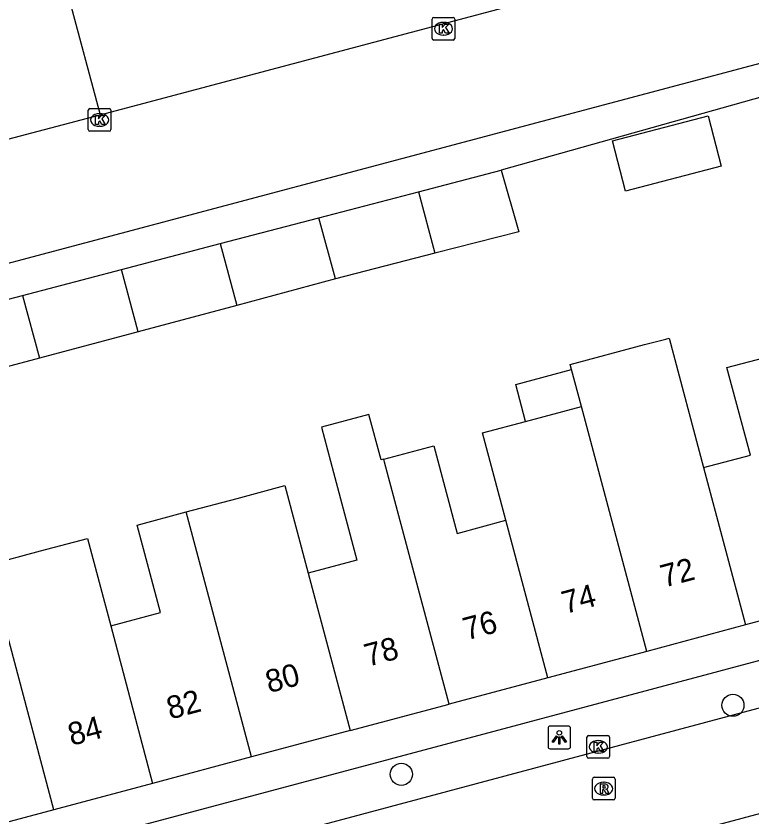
# Model space of a CAD drawing. Extents: x 162542 to 163144, y 380786 to 381511.
# Drawn here: x 162861.37 to 162893.88, y 381087.73 to 381123.11 of the extents above; entities that cross this region are included whole.
import ezdxf

# ---------------------------------------------------------------- set-up
doc = ezdxf.new("R2010")
doc.units = 0
for name, color, linetype in [('IMGEO_Boom', 7, 'Continuous'), ('IMGEO_Kolk', 7, 'Continuous'), ('IMGEO_Lichtpunt', 7, 'Continuous'), ('IMGEO_Pand', 7, 'Continuous'), ('IMGEO_Pand_nummerreeks', 7, 'Continuous'), ('IMGEO_Rijbaan_lokaal_open', 7, 'Continuous'), ('IMGEO_Rioolput', 7, 'Continuous'), ('IMGEO_Voetpad_open', 7, 'Continuous')]:
    doc.layers.add(name, color=color, linetype=linetype)

msp = doc.modelspace()

# ---------------------------------------------------------------- linework, layer by layer
at = {"layer": 'IMGEO_Boom'}
for centre in [(162893.042, 381092.664), (162878.397, 381089.614)]:
    msp.add_circle(centre, 0.489, dxfattribs=at)
at = {"layer": 'IMGEO_Kolk'}
for p, q in [((162879.756, 381122.122), (162879.756, 381122.974)), ((162879.831, 381123.048), (162880.683, 381123.048)), ((162880.757, 381122.974), (162880.757, 381122.122)), ((162880.244, 381122.828), (162880.269, 381122.828)), ((162880.267, 381122.268), (162880.242, 381122.268)), ((162880.683, 381122.048), (162879.831, 381122.048)), ((162864.642, 381119.019), (162865.494, 381119.019)), ((162864.567, 381118.093), (162864.567, 381118.945)), ((162865.055, 381118.799), (162865.08, 381118.799)), ((162865.568, 381118.945), (162865.568, 381118.093)), ((162865.494, 381118.019), (162864.642, 381118.019)), ((162865.078, 381118.239), (162865.053, 381118.239)), ((162886.593, 381090.4), (162886.593, 381091.252)), ((162886.668, 381091.326), (162887.52, 381091.326)), ((162887.081, 381091.106), (162887.106, 381091.106)), ((162887.594, 381091.252), (162887.594, 381090.4)), ((162887.52, 381090.326), (162886.668, 381090.326)), ((162887.104, 381090.546), (162887.079, 381090.546))]:
    msp.add_line(p, q, dxfattribs=at)
for points in [[(162879.756, 381122.122), (162879.756, 381122.974)], [(162879.831, 381123.048), (162880.683, 381123.048)], [(162880.757, 381122.974), (162880.757, 381122.122)], [(162880.077, 381122.748), (162880.2, 381122.748), (162880.2, 381122.597), (162880.33, 381122.748), (162880.494, 381122.748), (162880.348, 381122.597), (162880.501, 381122.348), (162880.349, 381122.348), (162880.264, 381122.512), (162880.2, 381122.445), (162880.2, 381122.348), (162880.077, 381122.348), (162880.077, 381122.748)], [(162880.683, 381122.048), (162879.831, 381122.048)], [(162864.642, 381119.019), (162865.494, 381119.019)], [(162864.567, 381118.093), (162864.567, 381118.945)], [(162864.888, 381118.719), (162865.011, 381118.719), (162865.011, 381118.568), (162865.141, 381118.719), (162865.305, 381118.719), (162865.159, 381118.568), (162865.312, 381118.319), (162865.16, 381118.319), (162865.075, 381118.483), (162865.011, 381118.416), (162865.011, 381118.319), (162864.888, 381118.319), (162864.888, 381118.719)], [(162865.568, 381118.945), (162865.568, 381118.093)], [(162865.494, 381118.019), (162864.642, 381118.019)], [(162886.593, 381090.4), (162886.593, 381091.252)], [(162886.668, 381091.326), (162887.52, 381091.326)], [(162886.914, 381091.026), (162887.037, 381091.026), (162887.037, 381090.875), (162887.167, 381091.026), (162887.331, 381091.026), (162887.185, 381090.875), (162887.338, 381090.626), (162887.186, 381090.626), (162887.101, 381090.79), (162887.037, 381090.723), (162887.037, 381090.626), (162886.914, 381090.626), (162886.914, 381091.026)], [(162887.594, 381091.252), (162887.594, 381090.4)], [(162887.52, 381090.326), (162886.668, 381090.326)]]:
    msp.add_lwpolyline(points, dxfattribs=at)
for centre, start, end in [((162879.833, 381122.972), 91.552, 178.448), ((162879.833, 381122.972), 91.552, 178.448), ((162880.681, 381122.972), 1.552, 88.448), ((162880.681, 381122.972), 1.552, 88.448), ((162879.833, 381122.124), 181.552, 268.448), ((162879.833, 381122.124), 181.552, 268.448), ((162880.681, 381122.124), 271.552, 358.448), ((162880.681, 381122.124), 271.552, 358.448), ((162864.644, 381118.943), 91.552, 178.448), ((162864.644, 381118.943), 91.552, 178.448), ((162865.492, 381118.943), 1.552, 88.448), ((162865.492, 381118.943), 1.552, 88.448), ((162864.644, 381118.095), 181.552, 268.448), ((162864.644, 381118.095), 181.552, 268.448), ((162865.492, 381118.095), 271.552, 358.448), ((162865.492, 381118.095), 271.552, 358.448), ((162886.67, 381091.25), 91.552, 178.448), ((162886.67, 381091.25), 91.552, 178.448), ((162887.518, 381091.25), 1.552, 88.448), ((162887.518, 381091.25), 1.552, 88.448), ((162886.67, 381090.402), 181.552, 268.448), ((162886.67, 381090.402), 181.552, 268.448), ((162887.518, 381090.402), 271.552, 358.448), ((162887.518, 381090.402), 271.552, 358.448)]:
    msp.add_arc(centre, 0.0765, start, end, dxfattribs=at)
for centre, major_axis, ratio, start_param, end_param in [((162880.243, 381122.548), (-0.387, 0.002), 0.722429, 4.712389, 7.853982), ((162880.268, 381122.548), (-0.39, 0.002), 0.717154, 1.570796, 4.712389), ((162865.054, 381118.519), (-0.387, 0.002), 0.722429, 4.712389, 7.853982), ((162865.079, 381118.519), (-0.39, 0.002), 0.717154, 1.570796, 4.712389), ((162887.08, 381090.826), (-0.387, 0.002), 0.722429, 4.712389, 7.853982), ((162887.105, 381090.826), (-0.39, 0.002), 0.717154, 1.570796, 4.712389)]:
    msp.add_ellipse(centre, major_axis=major_axis, ratio=ratio, start_param=start_param, end_param=end_param, dxfattribs=at)
at = {"layer": 'IMGEO_Lichtpunt'}
for p, q in [((162885.777, 381091.741), (162884.969, 381091.741)), ((162885.777, 381091.741), (162884.969, 381091.741)), ((162884.875, 381091.646), (162884.875, 381090.839)), ((162884.875, 381091.646), (162884.875, 381090.839)), ((162885.871, 381090.839), (162885.871, 381091.646)), ((162885.871, 381090.839), (162885.871, 381091.646)), ((162884.969, 381090.745), (162885.777, 381090.745)), ((162884.969, 381090.745), (162885.777, 381090.745))]:
    msp.add_line(p, q, dxfattribs=at)
for points in [[(162885.249, 381091.31), (162885.288, 381091.282), (162885.1, 381091.02), (162885.062, 381091.047), (162885.249, 381091.31)], [(162885.351, 381091.262), (162885.398, 381091.262), (162885.398, 381090.94), (162885.351, 381090.94), (162885.351, 381091.262)], [(162885.461, 381091.282), (162885.499, 381091.309), (162885.686, 381091.047), (162885.647, 381091.019), (162885.461, 381091.282)]]:
    msp.add_lwpolyline(points, dxfattribs=at)
msp.add_circle((162885.374, 381091.444), 0.0994, dxfattribs=at)
for centre, start, end in [((162884.969, 381091.646), 90, 180), ((162884.969, 381091.646), 90, 180), ((162885.777, 381091.646), 0, 90), ((162885.777, 381091.646), 0, 90), ((162884.969, 381090.839), 180, 270), ((162884.969, 381090.839), 180, 270), ((162885.777, 381090.839), 270, 0), ((162885.777, 381090.839), 270, 360)]:
    msp.add_arc(centre, 0.0946, start, end, dxfattribs=at)
at = {"layer": 'IMGEO_Pand'}
for points in [[(162887.719, 381117.591), (162891.943, 381118.698), (162892.524, 381116.476), (162888.294, 381115.37), (162887.719, 381117.591)], [(162879.15, 381115.349), (162882.812, 381116.307)], [(162882.812, 381116.307), (162883.589, 381113.582), (162879.878, 381112.64)], [(162874.757, 381114.199), (162879.15, 381115.349)], [(162879.15, 381115.349), (162879.878, 381112.64)], [(162870.394, 381113.056), (162874.757, 381114.199)], [(162875.481, 381111.506), (162874.757, 381114.199)], [(162866.036, 381111.915), (162870.394, 381113.056)], [(162870.394, 381113.056), (162871.121, 381110.329)], [(162879.878, 381112.64), (162875.481, 381111.506)], [(162861.666, 381110.771), (162866.036, 381111.915)], [(162866.769, 381109.164), (162866.036, 381111.915)], [(162875.481, 381111.506), (162871.121, 381110.329)], [(162857.295, 381109.627), (162861.666, 381110.771)], [(162861.666, 381110.771), (162862.404, 381108)], [(162871.121, 381110.329), (162866.769, 381109.164)], [(162866.769, 381109.164), (162862.404, 381108)], [(162885.916, 381107.496), (162885.857, 381107.716), (162889.141, 381108.593), (162890.074, 381108.842), (162890.223, 381108.882), (162891.746, 381103.164)], [(162862.404, 381108), (162858.038, 381106.837)], [(162891.746, 381103.164), (162893.813, 381103.716), (162892.781, 381107.58), (162895.082, 381108.194)], [(162883.882, 381105.204), (162883.446, 381106.836), (162885.916, 381107.496)], [(162886.351, 381105.863), (162885.916, 381107.496)], [(162883.882, 381105.204), (162886.351, 381105.863)], [(162889.234, 381095.043), (162886.351, 381105.863)], [(162877.622, 381103.533), (162877.501, 381103.501), (162876.964, 381105.51), (162874.863, 381104.948), (162875.4, 381102.939), (162876.432, 381099.075), (162874.285, 381098.501)], [(162883.015, 381100.833), (162881.983, 381104.697), (162883.882, 381105.204)], [(162877.622, 381103.533), (162879.825, 381104.121), (162880.857, 381100.257), (162883.015, 381100.833)], [(162880.504, 381092.712), (162877.656, 381103.404), (162877.622, 381103.533)], [(162891.746, 381103.164), (162893.599, 381096.209)], [(162868.891, 381101.201), (162871.14, 381101.801), (162873.253, 381102.365), (162874.285, 381098.501)], [(162865.556, 381096.171), (162867.756, 381096.758), (162866.724, 381100.622), (162868.891, 381101.201)], [(162871.774, 381090.38), (162868.891, 381101.201)], [(162884.868, 381093.877), (162883.015, 381100.833)], [(162860.16, 381098.87), (162862.454, 381099.482), (162864.525, 381100.035), (162865.556, 381096.171)], [(162863.043, 381088.048), (162860.16, 381098.87)], [(162874.285, 381098.501), (162876.139, 381091.546)], [(162897.964, 381097.375), (162893.599, 381096.209)], [(162865.556, 381096.171), (162867.409, 381089.214)], [(162893.599, 381096.209), (162889.234, 381095.043)], [(162889.234, 381095.043), (162884.868, 381093.877)], [(162884.868, 381093.877), (162880.504, 381092.712)], [(162876.139, 381091.546), (162880.504, 381092.712)], [(162876.139, 381091.546), (162871.774, 381090.38)], [(162871.774, 381090.38), (162867.409, 381089.214)], [(162867.409, 381089.214), (162863.043, 381088.048)], [(162863.043, 381088.048), (162858.678, 381086.882)]]:
    msp.add_lwpolyline(points, dxfattribs=at)
at = {"layer": 'IMGEO_Rijbaan_lokaal_open'}
for points in [[(162865.087, 381118.745), (162917.722, 381132.729)], [(162901.741, 381122.714), (162901.595, 381122.971), (162820.992, 381101.538), (162820.968, 381101.532)], [(162860.735, 381117.589), (162865.087, 381118.745)], [(162905.759, 381095.626), (162875.371, 381087.503), (162868.302, 381085.609)], [(162871.254, 381081.738), (162906.341, 381091.119)]]:
    msp.add_lwpolyline(points, dxfattribs=at)
at = {"layer": 'IMGEO_Rioolput'}
for p, q in [((162886.835, 381088.554), (162886.835, 381089.406)), ((162886.91, 381089.48), (162887.762, 381089.48)), ((162887.323, 381089.26), (162887.348, 381089.26)), ((162887.836, 381089.406), (162887.836, 381088.554)), ((162887.346, 381088.7), (162887.321, 381088.7)), ((162887.762, 381088.48), (162886.91, 381088.48))]:
    msp.add_line(p, q, dxfattribs=at)
for points in [[(162886.835, 381088.554), (162886.835, 381089.406)], [(162886.91, 381089.48), (162887.762, 381089.48)], [(162887.836, 381089.406), (162887.836, 381088.554)], [(162887.424, 381089.178), (162887.172, 381089.18), (162887.172, 381088.78)], [(162887.172, 381088.78), (162887.296, 381088.78), (162887.296, 381088.942), (162887.307, 381088.942)], [(162887.35, 381089.099), (162887.296, 381089.099), (162887.296, 381089.018)], [(162887.296, 381089.018), (162887.348, 381089.018)], [(162887.354, 381088.913), (162887.425, 381088.78), (162887.565, 381088.78), (162887.5, 381088.906)], [(162887.762, 381088.48), (162886.91, 381088.48)]]:
    msp.add_lwpolyline(points, dxfattribs=at)
for centre, radius, start, end in [((162886.912, 381089.404), 0.0765, 91.552, 178.448), ((162886.912, 381089.404), 0.0765, 91.552, 178.448), ((162887.76, 381089.404), 0.0765, 1.552, 88.448), ((162887.76, 381089.404), 0.0765, 1.552, 88.448), ((162887.306, 381088.889), 0.0533, 26.0293, 88.6989), ((162887.332, 381089.207), 0.19, 274.7715, 282.9687), ((162887.356, 381089.003), 0.0964, 77.0061, 93.1865), ((162887.37, 381089.06), 0.0378, 276.6634, 79.6772), ((162887.423, 381089.068), 0.109, 350.3612, 89.416), ((162887.421, 381089.068), 0.112, 277.5842, 350.9817), ((162887.405, 381088.853), 0.108, 29.5134, 73.7905), ((162886.912, 381088.556), 0.0765, 181.552, 268.448), ((162886.912, 381088.556), 0.0765, 181.552, 268.448), ((162887.76, 381088.556), 0.0765, 271.552, 358.448), ((162887.76, 381088.556), 0.0765, 271.552, 358.448)]:
    msp.add_arc(centre, radius, start, end, dxfattribs=at)
for centre, major_axis, ratio, start_param, end_param in [((162887.322, 381088.98), (-0.387, 0.002), 0.722429, 4.712389, 7.853982), ((162887.347, 381088.98), (-0.39, 0.002), 0.717154, 1.570796, 4.712389)]:
    msp.add_ellipse(centre, major_axis=major_axis, ratio=ratio, start_param=start_param, end_param=end_param, dxfattribs=at)
at = {"layer": 'IMGEO_Voetpad_open'}
for points in [[(162863.692, 381123.971), (162865.087, 381118.745)], [(162896.588, 381120.178), (162882.812, 381116.307)], [(162829.44, 381077.293), (162857.097, 381084.74), (162857.529, 381083.089), (162861.656, 381084.179), (162861.251, 381085.851), (162866.655, 381087.296), (162874.876, 381089.481), (162907.148, 381098.095), (162922.391, 381102.163), (162922.875, 381100.201)]]:
    msp.add_lwpolyline(points, dxfattribs=at)

# ---------------------------------------------------------------- texts
at = {"layer": 'IMGEO_Pand_nummerreeks'}
for s, rotation, p in [('72', 14.9542, (162889.995, 381097.855)), ('74', 14.9542, (162885.636, 381096.691)), ('76', 14.9536, (162881.274, 381095.525)), ('78', 14.9542, (162876.914, 381094.362)), ('80', 14.9536, (162872.551, 381093.196)), ('82', 14.9536, (162868.184, 381092.029)), ('84', 14.9536, (162863.825, 381090.865))]:
    msp.add_text(s, height=1, rotation=rotation, dxfattribs=at).set_placement(p)

doc.saveas('drawing.dxf')
